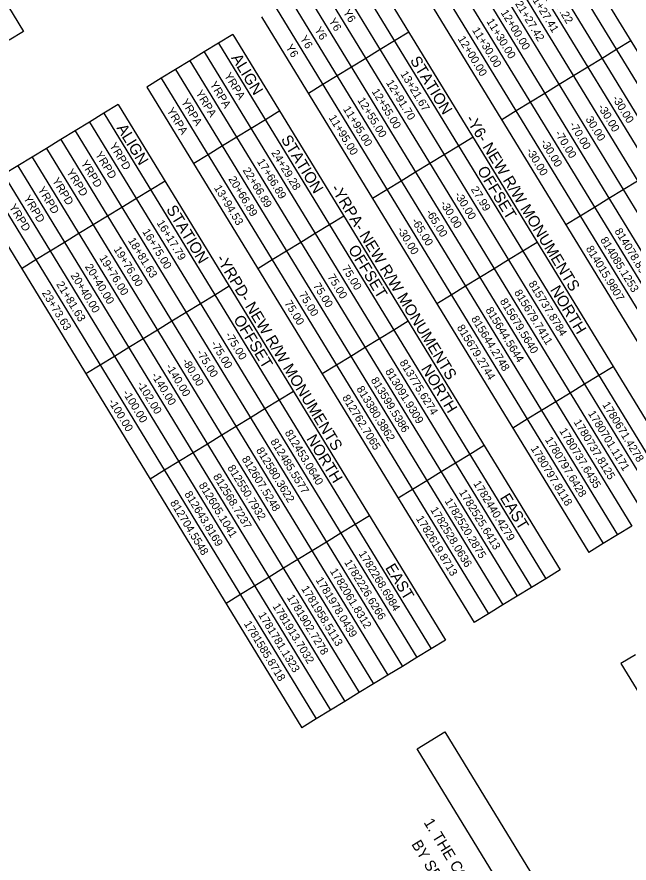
# Model space of a CAD drawing. Extents: x 1753086 to 1770987, y 792577 to 812636.
# Drawn here: x 1756968 to 1760334, y 800134 to 804785 of the extents above; entities that cross this region are included whole.
import ezdxf

# ---------------------------------------------------------------- set-up
doc = ezdxf.new("R2010")
doc.units = 0
for name, color, linetype in [('CTL Sheet Border CELL', 7, 'Continuous'), ('CTL Sheet Notes CELL', 7, 'Continuous'), ('CTL Sheet Table Cell', 7, 'Continuous'), ('CTL Sheet Text', 7, 'Continuous'), ('Old_Level_2', 7, 'Continuous')]:
    doc.layers.add(name, color=color, linetype=linetype)

msp = doc.modelspace()

# ---------------------------------------------------------------- linework, layer by layer
at = {"layer": 'CTL Sheet Border CELL'}
msp.add_lwpolyline([(1759320.2, 800854.1), (1761948.9, 796551.8), (1761798.1, 796459.7), (1759169.5, 800761.8)], close=True, dxfattribs=at)
at = {"layer": 'CTL Sheet Table Cell'}
for p, q in [((1755655.5, 806912.2), (1757004.4, 804704.5)), ((1759733, 805652), (1761531.5, 802708.4)), ((1759654.1, 805603.9), (1761452.7, 802660.2)), ((1759575.3, 805555.7), (1761373.8, 802612.1)), ((1759496.4, 805507.5), (1761295, 802563.9)), ((1759417.6, 805459.3), (1761216.1, 802515.7)), ((1759338.7, 805411.2), (1761137.3, 802467.5)), ((1759259.9, 805363), (1761058.4, 802419.4)), ((1759181, 805314.8), (1760979.6, 802371.2)), ((1759102.2, 805266.6), (1760900.7, 802323)), ((1759023.3, 805218.5), (1760821.9, 802274.8)), ((1758865.6, 805122.1), (1760664.2, 802178.5)), ((1758786.8, 805073.9), (1760585.4, 802130.3)), ((1758707.9, 805025.8), (1760506.5, 802082.1)), ((1758629.1, 804977.6), (1760427.7, 802034)), ((1758550.3, 804929.4), (1760348.8, 801985.8)), ((1758471.4, 804881.2), (1760270, 801937.6)), ((1758392.6, 804833.1), (1760191.1, 801889.4)), ((1758313.7, 804784.9), (1760112.3, 801841.3)), ((1757004.4, 804704.5), (1756925.6, 804656.3)), ((1759122.6, 804701.6), (1759043.7, 804653.4)), ((1758156, 804688.5), (1758077.2, 804640.4)), ((1758156, 804688.5), (1759954.6, 801744.9)), ((1758077.2, 804640.4), (1757998.3, 804592.2)), ((1758077.2, 804640.4), (1759875.7, 801696.7)), ((1759043.7, 804653.4), (1758964.9, 804605.2)), ((1760343.2, 804653.3), (1760264.3, 804605.1)), ((1757998.3, 804592.2), (1757919.5, 804544)), ((1757998.3, 804592.2), (1759796.9, 801648.6)), ((1758964.9, 804605.2), (1758886, 804557.1)), ((1760264.3, 804605.1), (1760185.5, 804557)), ((1757919.5, 804544), (1757840.6, 804495.8)), ((1757919.5, 804544), (1759718, 801600.4)), ((1758886, 804557.1), (1758807.2, 804508.9)), ((1760185.5, 804557), (1760106.6, 804508.8)), ((1757840.6, 804495.8), (1757761.8, 804447.7)), ((1757840.6, 804495.8), (1759639.2, 801552.2)), ((1758807.2, 804508.9), (1758728.3, 804460.7)), ((1760106.6, 804508.8), (1760027.8, 804460.6)), ((1757761.8, 804447.7), (1757682.9, 804399.5)), ((1757761.8, 804447.7), (1759560.3, 801504)), ((1758728.3, 804460.7), (1758649.5, 804412.5)), ((1760027.8, 804460.6), (1759949, 804412.4)), ((1757682.9, 804399.5), (1759481.5, 801455.9)), ((1758649.5, 804412.5), (1758570.6, 804364.4)), ((1759949, 804412.4), (1759870.1, 804364.3)), ((1759870.1, 804364.3), (1759791.3, 804316.1)), ((1757525.2, 804303.1), (1757446.4, 804254.9)), ((1757525.2, 804303.1), (1759323.8, 801359.5)), ((1759791.3, 804316.1), (1759712.4, 804267.9)), ((1757446.4, 804254.9), (1757367.5, 804206.8)), ((1757446.4, 804254.9), (1759245, 801311.3)), ((1758413, 804268), (1758334.1, 804219.8)), ((1759712.4, 804267.9), (1759633.6, 804219.7)), ((1757367.5, 804206.8), (1757288.7, 804158.6)), ((1757367.5, 804206.8), (1759166.1, 801263.1)), ((1758334.1, 804219.8), (1758255.3, 804171.7)), ((1757288.7, 804158.6), (1757209.9, 804110.4)), ((1757288.7, 804158.6), (1759087.3, 801215)), ((1758255.3, 804171.7), (1758176.4, 804123.5)), ((1757209.9, 804110.4), (1757131, 804062.2)), ((1757209.9, 804110.4), (1759008.4, 801166.8)), ((1758176.4, 804123.5), (1758097.6, 804075.3)), ((1759475.9, 804123.4), (1759397, 804075.2)), ((1757131, 804062.2), (1757052.2, 804014.1)), ((1757131, 804062.2), (1758929.6, 801118.6)), ((1758097.6, 804075.3), (1758018.7, 804027.1)), ((1759397, 804075.2), (1759318.2, 804027)), ((1757052.2, 804014.1), (1756973.3, 803965.9)), ((1757052.2, 804014.1), (1758850.7, 801070.4)), ((1758018.7, 804027.1), (1757939.9, 803979)), ((1759318.2, 804027), (1759239.3, 803978.9)), ((1756973.3, 803965.9), (1756894.5, 803917.7)), ((1756973.3, 803965.9), (1758771.9, 801022.3)), ((1759239.3, 803978.9), (1759160.5, 803930.7)), ((1756894.5, 803917.7), (1758693, 800974.1)), ((1759160.5, 803930.7), (1759081.6, 803882.5)), ((1756815.6, 803869.5), (1758614.2, 800925.9)), ((1757782.2, 803882.6), (1757703.3, 803834.4)), ((1759081.6, 803882.5), (1759002.8, 803834.3)), ((1760381.1, 803882.4), (1760302.2, 803834.2)), ((1756736.8, 803821.4), (1758535.3, 800877.7)), ((1757703.3, 803834.4), (1757624.5, 803786.3)), ((1759002.8, 803834.3), (1758923.9, 803786.2)), ((1760302.2, 803834.2), (1760223.4, 803786)), ((1757624.5, 803786.3), (1757545.6, 803738.1)), ((1760223.4, 803786), (1760144.5, 803737.9)), ((1757545.6, 803738.1), (1757466.8, 803689.9)), ((1760144.5, 803737.9), (1760065.7, 803689.7)), ((1757466.8, 803689.9), (1757387.9, 803641.7)), ((1758766.2, 803689.8), (1758687.4, 803641.6)), ((1760065.7, 803689.7), (1759986.8, 803641.5)), ((1757387.9, 803641.7), (1757309.1, 803593.6)), ((1758687.4, 803641.6), (1758608.5, 803593.4)), ((1757309.1, 803593.6), (1757230.2, 803545.4)), ((1758608.5, 803593.4), (1758529.7, 803545.3)), ((1757230.2, 803545.4), (1757151.4, 803497.2)), ((1758529.7, 803545.3), (1758450.9, 803497.1)), ((1759829.2, 803545.2), (1759750.3, 803497)), ((1757151.4, 803497.2), (1757072.6, 803449)), ((1758450.9, 803497.1), (1758372, 803448.9)), ((1759750.3, 803497), (1759671.5, 803448.8)), ((1757072.6, 803449), (1756993.7, 803400.9)), ((1758372, 803448.9), (1758293.2, 803400.7)), ((1759671.5, 803448.8), (1759592.6, 803400.6)), ((1759592.6, 803400.6), (1759513.8, 803352.5)), ((1759513.8, 803352.5), (1759434.9, 803304.3)), ((1758135.5, 803304.4), (1758056.6, 803256.2)), ((1759434.9, 803304.3), (1759356.1, 803256.1)), ((1758056.6, 803256.2), (1757977.8, 803208)), ((1759356.1, 803256.1), (1759277.2, 803207.9)), ((1757977.8, 803208), (1757898.9, 803159.9)), ((1757898.9, 803159.9), (1757820.1, 803111.7)), ((1757820.1, 803111.7), (1757741.2, 803063.5)), ((1759119.5, 803111.6), (1759040.7, 803063.4)), ((1757741.2, 803063.5), (1757662.4, 803015.3)), ((1759040.7, 803063.4), (1758961.8, 803015.2)), ((1757662.4, 803015.3), (1757583.5, 802967.2)), ((1758961.8, 803015.2), (1758883, 802967.1)), ((1757583.5, 802967.2), (1757504.7, 802919)), ((1758883, 802967.1), (1758804.1, 802918.9)), ((1757504.7, 802919), (1757425.8, 802870.8)), ((1758804.1, 802918.9), (1758725.3, 802870.7)), ((1757425.8, 802870.8), (1757347, 802822.6)), ((1758725.3, 802870.7), (1758646.4, 802822.5)), ((1760246.7, 802861.8), (1760167.8, 802813.7)), ((1760167.8, 802813.7), (1760089, 802765.5)), ((1760089, 802765.5), (1760010.1, 802717.3)), ((1758488.8, 802726.2), (1758409.9, 802678)), ((1760010.1, 802717.3), (1759931.3, 802669.1)), ((1758409.9, 802678), (1758331.1, 802629.8)), ((1759931.3, 802669.1), (1759852.4, 802620.9)), ((1758331.1, 802629.8), (1758252.2, 802581.7)), ((1759852.4, 802620.9), (1759773.6, 802572.8)), ((1758252.2, 802581.7), (1758173.4, 802533.5)), ((1759773.6, 802572.8), (1759694.7, 802524.6)), ((1758173.4, 802533.5), (1758094.5, 802485.3)), ((1758094.5, 802485.3), (1758015.7, 802437.1)), ((1758015.7, 802437.1), (1757936.8, 802389)), ((1759537.1, 802428.2), (1759458.2, 802380.1)), ((1757936.8, 802389), (1757858, 802340.8)), ((1759458.2, 802380.1), (1759379.4, 802331.9)), ((1757858, 802340.8), (1757779.1, 802292.6)), ((1759379.4, 802331.9), (1759300.5, 802283.7)), ((1757779.1, 802292.6), (1757700.3, 802244.4)), ((1759300.5, 802283.7), (1759221.7, 802235.5)), ((1759221.7, 802235.5), (1759142.8, 802187.4)), ((1759142.8, 802187.4), (1759064, 802139.2)), ((1758906.3, 802042.8), (1758827.4, 801994.7)), ((1758827.4, 801994.7), (1758748.6, 801946.5)), ((1760348.8, 801985.8), (1760270, 801937.6)), ((1758748.6, 801946.5), (1758669.7, 801898.3)), ((1760270, 801937.6), (1760191.1, 801889.4)), ((1758669.7, 801898.3), (1758590.9, 801850.1)), ((1760191.1, 801889.4), (1760112.3, 801841.3)), ((1758590.9, 801850.1), (1758512, 801802)), ((1758512, 801802), (1758433.2, 801753.8)), ((1758433.2, 801753.8), (1758354.3, 801705.6)), ((1759954.6, 801744.9), (1759875.7, 801696.7)), ((1758354.3, 801705.6), (1758275.5, 801657.4)), ((1759875.7, 801696.7), (1759796.9, 801648.6)), ((1758275.5, 801657.4), (1758196.7, 801609.3)), ((1759796.9, 801648.6), (1759718, 801600.4)), ((1758196.7, 801609.3), (1758117.8, 801561.1)), ((1759718, 801600.4), (1759639.2, 801552.2)), ((1759639.2, 801552.2), (1759560.3, 801504)), ((1759560.3, 801504), (1759481.5, 801455.9)), ((1759323.8, 801359.5), (1759245, 801311.3)), ((1759245, 801311.3), (1759166.1, 801263.1)), ((1759166.1, 801263.1), (1759087.3, 801215)), ((1760369, 801278.6), (1760289.3, 801229.9)), ((1759087.3, 801215), (1759008.4, 801166.8)), ((1760289.3, 801229.9), (1762108.3, 798252.8)), ((1759008.4, 801166.8), (1758929.6, 801118.6)), ((1758929.6, 801118.6), (1758850.7, 801070.4)), ((1758850.7, 801070.4), (1758771.9, 801022.3)), ((1758771.9, 801022.3), (1758693, 800974.1)), ((1758693, 800974.1), (1758614.2, 800925.9)), ((1758614.2, 800925.9), (1758535.3, 800877.7))]:
    msp.add_line(p, q, dxfattribs=at)

# ---------------------------------------------------------------- texts
at = {"layer": 'CTL Sheet Notes CELL'}
for s, p in [('ALIGN', (1758144.4, 804559.8)), ('STATION', (1759127.3, 804546.2)), ('-Y6- NEW R/W MONUMENTS', (1759432.9, 804223.3)), ('ALIGN', (1757513.7, 804174.4)), ('STATION', (1758417.7, 804112.6)), ('OFFSET', (1759496.5, 803941.9)), ('-YRPA- NEW R/W MONUMENTS', (1758691.4, 803841.9)), ('STATION', (1757786.9, 803727.2)), ('OFFSET', (1758786.9, 803508.3)), ('-YRPD- NEW R/W MONUMENTS', (1758060.6, 803456.5)), ('NORTH', (1759897.9, 803285)), ('OFFSET', (1758156.1, 803122.9)), ('NORTH', (1759188.2, 802851.5)), ('NORTH', (1758557.5, 802466.1)), ('EAST', (1759621.7, 802142)), ('EAST', (1758990.9, 801756.6))]:
    msp.add_text(s, height=61.6, rotation=301.4249, dxfattribs=at).set_placement(p)
at = {"layer": 'CTL Sheet Text'}
for s, p in [('17+87.22', (1759863.4, 804953.3)), ('21+27.41', (1759784.6, 804905.1)), ('21+27.42', (1759705.7, 804857)), ('Y6', (1758759.3, 804811)), ('12+00.00', (1759626.9, 804808.8)), ('Y6', (1758680.4, 804762.8)), ('11+30.00', (1759548, 804760.6)), ('Y6', (1758601.6, 804714.6)), ('11+30.00', (1759469.2, 804712.4)), ('Y6', (1758522.7, 804666.5)), ('12+00.00', (1759390.3, 804664.2)), ('Y6', (1758443.9, 804618.3)), ('YRPA', (1758105.7, 804462.8)), ('13+21.67', (1759074.9, 804471.5)), ('YRPA', (1758026.9, 804414.7)), ('12+91.70', (1758996.1, 804423.4)), ('YRPA', (1757948, 804366.5)), ('12+55.00', (1758917.2, 804375.2)), ('YRPA', (1757869.2, 804318.3)), ('12+55.00', (1758838.4, 804327)), ('-30.00', (1760239.5, 804337.8)), ('YRPA', (1757790.3, 804270.1)), ('11+95.00', (1758759.5, 804278.8)), ('-30.00', (1760160.6, 804289.7)), ('11+95.00', (1758680.7, 804230.7)), ('30.00', (1760093.1, 804222.9)), ('-70.00', (1760002.9, 804193.3)), ('-70.00', (1759924.1, 804145.1)), ('YRPD', (1757474.9, 804077.4)), ('-30.00', (1759845.2, 804097)), ('YRPD', (1757396.1, 804029.2)), ('24+29.28', (1758365.3, 804038)), ('-30.00', (1759766.4, 804048.8)), ('17+66.89', (1758286.5, 803989.8)), ('YRPD', (1757317.2, 803981.1)), ('22+66.89', (1758207.6, 803941.6)), ('YRPD', (1757238.4, 803932.9)), ('YRPD', (1757159.6, 803884.7)), ('20+66.89', (1758128.8, 803893.4)), ('YRPD', (1757080.7, 803836.5)), ('13+94.53', (1758049.9, 803845.3)), ('27.99', (1759462.4, 803837.5)), ('YRPD', (1757001.9, 803788.4)), ('-30.00', (1759372.1, 803807.9)), ('YRPD', (1756923, 803740.2)), ('-30.00', (1759293.3, 803759.7)), ('-65.00', (1759214.4, 803711.6)), ('16+17.79', (1757734.5, 803652.6)), ('-65.00', (1759135.6, 803663.4)), ('16+75.00', (1757655.7, 803604.4)), ('-30.00', (1759056.7, 803615.2)), ('814078.8909', (1760252.6, 803607.5)), ('18+81.63', (1757576.8, 803556.2)), ('814085.1253', (1760173.7, 803559.3)), ('19+76.00', (1757498, 803508)), ('814015.9807', (1760094.9, 803511.1)), ('19+76.00', (1757419.1, 803459.9)), ('20+40.00', (1757340.3, 803411.7)), ('75.00', (1758752.7, 803403.9)), ('20+40.00', (1757261.4, 803363.5)), ('75.00', (1758673.9, 803355.7)), ('21+81.63', (1757182.6, 803315.3)), ('75.00', (1758595, 803307.5)), ('815737.8784', (1759779.5, 803318.4)), ('23+73.63', (1757103.8, 803267.2)), ('75.00', (1758516.2, 803259.4)), ('815679.7411', (1759700.6, 803270.3)), ('75.00', (1758437.3, 803211.2)), ('815679.5640', (1759621.8, 803222.1)), ('815644.5644', (1759542.9, 803173.9)), ('815644.2748', (1759464.1, 803125.7)), ('815679.2744', (1759385.2, 803077.6)), ('-75.00', (1758110.6, 803037.1)), ('-75.00', (1758031.7, 802988.9)), ('-75.00', (1757952.9, 802940.7)), ('-80.00', (1757874, 802892.6)), ('813775.6274', (1759069.9, 802884.9)), ('-140.00', (1757783.8, 802863)), ('813091.9309', (1758991, 802836.7)), ('-140.00', (1757705, 802814.8)), ('813599.5386', (1758912.2, 802788.5)), ('-102.00', (1757626.1, 802766.7)), ('813380.3862', (1758833.3, 802740.3)), ('-100.00', (1757547.3, 802718.5)), ('812762.7065', (1758754.5, 802692.2)), ('-100.00', (1757468.4, 802670.3)), ('1780671.4278', (1760185.6, 802653.7)), ('1780701.1171', (1760106.8, 802605.5)), ('1780737.8125', (1760027.9, 802557.4)), ('812453.0640', (1758439.1, 802499.4)), ('1780737.6435', (1759949.1, 802509.2)), ('1780797.6428', (1759870.2, 802461)), ('812485.5577', (1758360.2, 802451.3)), ('1780797.8118', (1759791.4, 802412.8)), ('812580.3622', (1758281.4, 802403.1)), ('812607.5248', (1758202.5, 802354.9)), ('812550.7932', (1758123.7, 802306.7)), ('812568.7237', (1758044.8, 802258.6)), ('812605.1041', (1757966, 802210.4)), ('1782440.4279', (1759476, 802220.1)), ('812643.8169', (1757887.2, 802162.2)), ('1782525.6413', (1759397.2, 802172)), ('812704.5548', (1757808.3, 802114)), ('1782520.2875', (1759318.3, 802123.8)), ('1782528.0636', (1759239.5, 802075.6)), ('1782619.8713', (1759160.6, 802027.4)), ('1782268.6984', (1758845.2, 801834.7)), ('1782226.6266', (1758766.4, 801786.6)), ('1782061.8312', (1758687.5, 801738.4)), ('1781978.0439', (1758608.7, 801690.2)), ('1781958.5113', (1758529.8, 801642)), ('1781902.7278', (1758451, 801593.9)), ('1781913.7032', (1758372.1, 801545.7)), ('1781781.1323', (1758293.3, 801497.5)), ('1781585.8718', (1758214.4, 801449.3))]:
    msp.add_text(s, height=44, rotation=301.4249, dxfattribs=at).set_placement(p)
at = {"layer": 'Old_Level_2'}
for s, p in [('1. THE CONTROL DATA FOR THIS PROJECT CAN BE FOUND ELECTRONICALLY', (1759202.6, 800357.2)), ('   BY SELECTING PROJECT CONTROL DATA AT:', (1759100.2, 800294.7))]:
    msp.add_text(s, height=60, rotation=301.4249, dxfattribs=at).set_placement(p)

doc.saveas('drawing.dxf')
